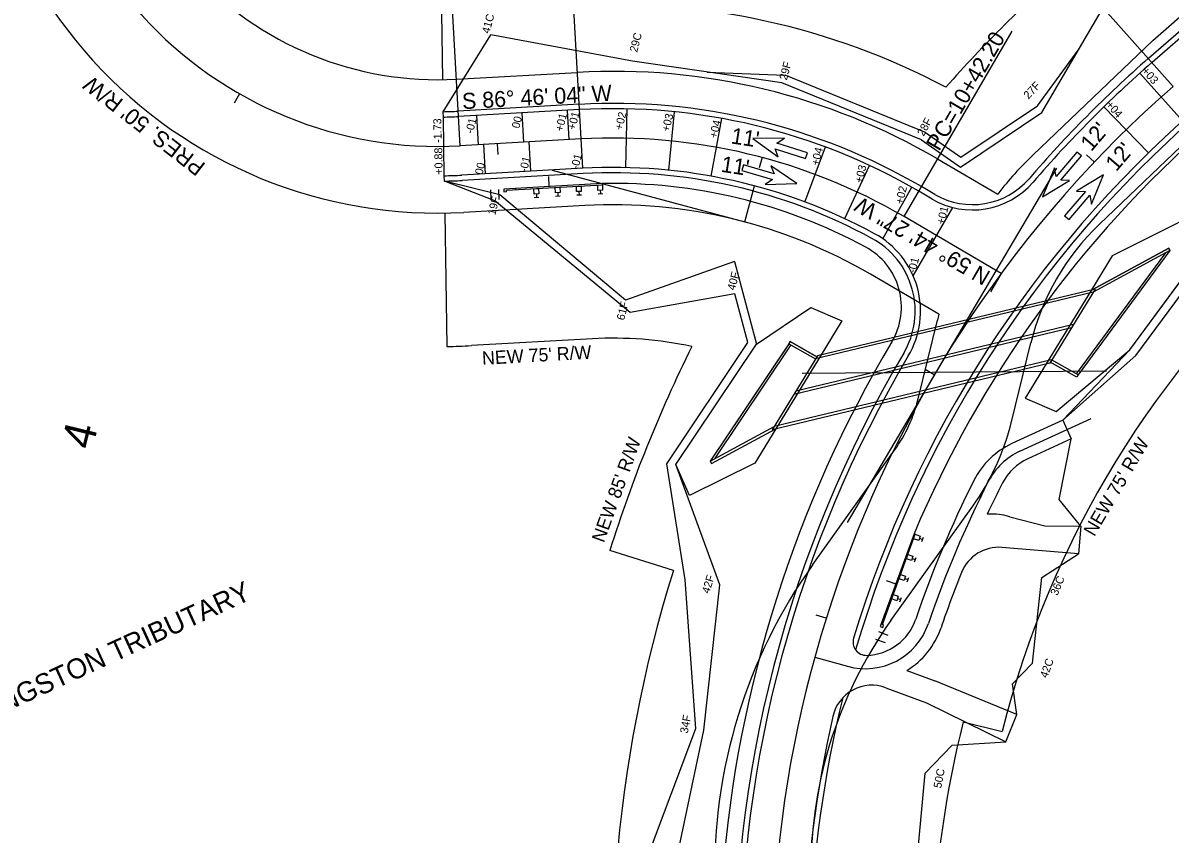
# Model space of a CAD drawing. Extents: x 1579440 to 1580937, y 1116374 to 1119566.
# Drawn here: x 1579773.5 to 1580203.4, y 1117456.1 to 1117760.1 of the extents above; entities that cross this region are included whole.
import ezdxf

# ---------------------------------------------------------------- set-up
doc = ezdxf.new("R2010")
doc.units = 0
for name, color, linetype in [('BR_CENTER LINES', 7, 'Continuous'), ('RD_EX_DV_TX_Prop', 7, 'Continuous'), ('RD_EX_RW', 7, 'Continuous'), ('RD_EX_RW_TX', 7, 'Continuous'), ('RD_EX_SU_Telecom', 7, 'Continuous'), ('RD_EX_VEG', 7, 'Continuous'), ('RD_HC_Cl', 7, 'Continuous'), ('RD_HC_CL_Rel', 7, 'Continuous'), ('RD_HC_Data', 7, 'Continuous'), ('RD_HC_Data_Tic', 7, 'Continuous'), ('RD_PD_ALT4_TX', 7, 'Continuous'), ('RD_PD_CstnLmt', 7, 'Continuous'), ('RD_PD_CstnLmt_TX', 7, 'Continuous'), ('RD_PD_DR_ErosCtrl', 7, 'Continuous'), ('RD_PD_DR_FlowCtrl', 7, 'Continuous'), ('RD_PD_Driveway', 7, 'Continuous'), ('RD_PD_Final_TrvlWay', 7, 'Continuous'), ('RD_PD_Final_TX', 7, 'Continuous'), ('RD_PD_GR', 7, 'Continuous'), ('RD_PD_PatLn1', 7, 'Continuous'), ('RD_PD_PaveShd', 7, 'Continuous'), ('RD_PD_RW', 7, 'Continuous'), ('RD_Sketch1', 7, 'Continuous')]:
    doc.layers.add(name, color=color, linetype=linetype)

# ---------------------------------------------------------------- blocks, each defined once
blk = doc.blocks.new('Guardrail_MT2_Leading_with_Buffer')
at = {"layer": 'RD_PD_GR'}
for p, q in [((17.52, 4.7), (15.77, 4.61)), ((16.72, 3.41), (16.65, 4.66)), ((25.51, 5.13), (23.76, 5.04)), ((24.7, 3.84), (24.64, 5.09)), ((38.94, 2.11), (38.74, 5.85)), ((41.94, 2.27), (41.74, 6.01)), ((1.55, 3.84), (-0.2, 3.74)), ((-0.13, 2.5), (1.61, 2.59)), ((-0.03, 0.5), (-0.13, 2.5)), ((35.92, 2.44), (-0.03, 0.5)), ((1.72, 0.59), (-0.03, 0.5)), ((-0.03, 0.5), (0, 0)), ((0, 0), (36.95, 2)), ((0.74, 2.54), (0.67, 3.79)), ((1.61, 2.59), (1.72, 0.59)), ((9.53, 4.27), (7.79, 4.18)), ((7.85, 2.93), (9.6, 3.02)), ((7.96, 0.93), (7.85, 2.93)), ((9.71, 1.03), (7.96, 0.93)), ((8.73, 2.98), (8.66, 4.22)), ((9.6, 3.02), (9.71, 1.03)), ((15.84, 3.36), (17.59, 3.45)), ((15.95, 1.36), (15.84, 3.36)), ((17.7, 1.46), (15.95, 1.36)), ((17.59, 3.45), (17.7, 1.46)), ((20.17, -2.67), (19.97, 1.08)), ((23.83, 3.79), (25.58, 3.89)), ((23.94, 1.79), (23.83, 3.79)), ((25.69, 1.89), (23.94, 1.79)), ((25.58, 3.89), (25.69, 1.89)), ((32.43, 2.25), (32.45, 1.75)), ((36.89, 3), (35.89, 2.94)), ((35.89, 2.94), (35.92, 2.44)), ((36.95, 2), (36.89, 3))]:
    blk.add_line(p, q, dxfattribs=at)

msp = doc.modelspace()

# ---------------------------------------------------------------- linework, layer by layer
at = {"layer": 'BR_CENTER LINES'}
for p, q in [((1580160.85, 1117705.68), (1580082.37, 1117572.94)), ((1580179.56, 1117629.56), (1580065.5, 1117628.75))]:
    msp.add_line(p, q, dxfattribs=at)
at = {"layer": 'RD_EX_RW'}
for p, q in [((1580196.94, 1117753.53), (1580281.34, 1117827.39)), ((1580152.08, 1117710.69), (1580196.94, 1117753.53)), ((1579935.89, 1117738.99), (1579981.24, 1117741.55)), ((1580176.94, 1117684.65), (1580221.24, 1117726.96)), ((1580116.29, 1117709.09), (1580138.85, 1117695.93)), ((1579984.06, 1117691.63), (1579938.71, 1117689.07)), ((1580116.8, 1117650.91), (1580091.09, 1117665.9)), ((1580109.02, 1117619.23), (1580116.24, 1117648.72)), ((1580143.99, 1117610.66), (1580151.21, 1117640.16)), ((1580069.52, 1117557.1), (1580100.19, 1117599.99)), ((1580098.8, 1117536.16), (1580129.47, 1117579.05))]:
    msp.add_line(p, q, dxfattribs=at)
for centre, radius, start, end in [((1579928.87, 1117863.31), 174.52, 171.1236, 273.2323), ((1579928.87, 1117863.31), 124.52, 171.1236, 273.2323), ((1579994.83, 1117500.9), 241.03, 59.7409, 93.2323), ((1580240.27, 1117618.34), 127.69, 133.6822, 142.5831), ((1579994.83, 1117500.9), 191.03, 59.7409, 93.2323), ((1580240.27, 1117618.34), 91.69, 133.6822, 166.2368), ((1580240.27, 1117618.34), 127.69, 165.2247, 166.2368), ((1580054.66, 1117632.54), 55.96, 324.4316, 346.2368), ((1580054.66, 1117632.54), 91.96, 324.4316, 346.2368), ((1580229.76, 1117442.52), 197, 144.4316, 181.4941), ((1580229.76, 1117442.52), 161, 144.4316, 181.4941)]:
    msp.add_arc(centre, radius, start, end, dxfattribs=at)
at = {"layer": 'RD_EX_SU_Telecom'}
for p, q in [((1580201.66, 1117673.87), (1580168.27, 1117628.57)), ((1580203.38, 1117674.8), (1580169, 1117628.15)), ((1580202.91, 1117675.68), (1580174.18, 1117660.08)), ((1580203.38, 1117674.8), (1580174.55, 1117659.14)), ((1580203.38, 1117674.8), (1580202.91, 1117675.68)), ((1580175.28, 1117660.35), (1580071.24, 1117635.36)), ((1580175.28, 1117660.35), (1580158.29, 1117632.61)), ((1580174.55, 1117659.14), (1580070.5, 1117634.15)), ((1580173.91, 1117660.02), (1580156.92, 1117632.28)), ((1580166.42, 1117645.88), (1580062.38, 1117620.89)), ((1580167.16, 1117647.08), (1580063.12, 1117622.09)), ((1580060.5, 1117639.83), (1580031.07, 1117595.84)), ((1580061.23, 1117639.42), (1580032.64, 1117596.69)), ((1580060.5, 1117639.83), (1580061, 1117640.7)), ((1580060.5, 1117639.83), (1580070.5, 1117634.15)), ((1580061, 1117640.7), (1580071.03, 1117635.01)), ((1580071.24, 1117635.36), (1580054.25, 1117607.62)), ((1580072.62, 1117635.69), (1580055.63, 1117607.95)), ((1580158.29, 1117632.61), (1580054.25, 1117607.62)), ((1580159.03, 1117633.82), (1580054.99, 1117608.83)), ((1580168.51, 1117627.29), (1580158.51, 1117632.96)), ((1580169, 1117628.15), (1580159.03, 1117633.82)), ((1580169, 1117628.15), (1580168.51, 1117627.29)), ((1580031.07, 1117595.84), (1580054.99, 1117608.83)), ((1580031.54, 1117594.96), (1580055.35, 1117607.89)), ((1580031.07, 1117595.84), (1580031.54, 1117594.96))]:
    msp.add_line(p, q, dxfattribs=at)
at = {"layer": 'RD_HC_Cl'}
for p, q in [((1579982.65, 1117716.59), (1579937.3, 1117714.03)), ((1579982.65, 1117716.59), (1579937.3, 1117714.03)), ((1580140.15, 1117666.23), (1580103.69, 1117687.5)), ((1580140.15, 1117666.23), (1580103.69, 1117687.5))]:
    msp.add_line(p, q, dxfattribs=at)
for centre, radius, start, end in [((1579928.87, 1117863.31), 149.52, 171.1236, 273.2323), ((1579928.87, 1117863.31), 149.52, 171.1236, 273.2323), ((1579994.83, 1117500.9), 216.03, 59.7409, 93.2323), ((1579994.83, 1117500.9), 216.03, 59.7409, 93.2323)]:
    msp.add_arc(centre, radius, start, end, dxfattribs=at)
at = {"layer": 'RD_HC_CL_Rel'}
for p, q in [((1580147.11, 1117599.56), (1580173.86, 1117611.88)), ((1580070.23, 1117522.38), (1580082.5, 1117518.99))]:
    msp.add_line(p, q, dxfattribs=at)
for centre, radius, start, end in [((1580494.33, 1117405.17), 440, 131.1901, 190.2447), ((1580157.57, 1117576.85), 25, 114.7328, 152.988), ((1580494.33, 1117405.17), 403, 152.988, 161.2024), ((1580089.16, 1117543.08), 25, 254.5511, 341.2024)]:
    msp.add_arc(centre, radius, start, end, dxfattribs=at)
at = {"layer": 'RD_HC_Data'}
for p, q in [((1579982.65, 1117716.59), (1579975.95, 1117835.33)), ((1579937.3, 1117714.03), (1579930.72, 1117830.53)), ((1580204.6, 1117736.25), (1580127.53, 1117822.95)), ((1580103.69, 1117687.5), (1580144.19, 1117756.92))]:
    msp.add_line(p, q, dxfattribs=at)
at = {"layer": 'RD_HC_Data_Tic'}
for p, q in [((1579854.65, 1117733.51), (1579852.67, 1117730.04)), ((1579951.18, 1117714.81), (1579951.41, 1117710.82)), ((1580050.49, 1117709.64), (1580049.46, 1117705.77)), ((1580175.03, 1117707.91), (1580172.13, 1117710.66)), ((1580140.15, 1117666.23), (1580136.11, 1117659.32)), ((1580115.03, 1117628.18), (1580111.58, 1117630.2)), ((1580074.54, 1117536.98), (1580070.72, 1117538.17))]:
    msp.add_line(p, q, dxfattribs=at)
at = {"layer": 'RD_PD_ALT4_TX'}
for p, q in [((1580192.05, 1117741.22), (1580208.1, 1117723.38)), ((1579944.19, 1117714.41), (1579943.57, 1117725.4)), ((1579961.17, 1117715.37), (1579960.55, 1117726.36)), ((1579978.14, 1117716.33), (1579977.52, 1117727.31)), ((1579983.27, 1117705.6), (1579982.03, 1117727.57)), ((1579999.4, 1117705.88), (1579999.89, 1117727.87)), ((1580015.5, 1117704.89), (1580017.72, 1117726.77)), ((1580178.56, 1117728.58), (1580195.33, 1117711.41)), ((1580031.47, 1117702.63), (1580035.4, 1117724.28)), ((1579946.81, 1117703.55), (1579946.19, 1117714.53)), ((1579963.78, 1117704.5), (1579963.16, 1117715.49)), ((1580066.57, 1117692.97), (1580074.27, 1117713.58)), ((1580081.45, 1117686.74), (1580090.75, 1117706.68)), ((1580095.71, 1117679.21), (1580106.63, 1117698.5)), ((1580107.12, 1117665.33), (1580122.04, 1117690.9))]:
    msp.add_line(p, q, dxfattribs=at)
at = {"layer": 'RD_PD_CstnLmt'}
for p, q in [((1580155.41, 1117726.51), (1580183.29, 1117774.31)), ((1579931.01, 1117726.8), (1579948.88, 1117755.58)), ((1580001.96, 1117745.69), (1579948.88, 1117755.58)), ((1580057.96, 1117737.67), (1580001.96, 1117745.69)), ((1580110.29, 1117716.3), (1580057.96, 1117737.67)), ((1580124.9, 1117706.07), (1580155.41, 1117726.51)), ((1580110.29, 1117716.3), (1580124.9, 1117706.07)), ((1579952.26, 1117695.71), (1579931.41, 1117700.81)), ((1579999.36, 1117656.23), (1579952.26, 1117695.71)), ((1580188.37, 1117637.58), (1580223.44, 1117685.16)), ((1580040.1, 1117670.68), (1579999.36, 1117656.23)), ((1580040.1, 1117670.68), (1580048.41, 1117639.74)), ((1580018.2, 1117594.58), (1580048.41, 1117639.74)), ((1580163.18, 1117611.18), (1580188.37, 1117637.58)), ((1580161.89, 1117581.53), (1580166.38, 1117604.22)), ((1580034.6, 1117549.51), (1580018.2, 1117594.58)), ((1580169.96, 1117571.45), (1580161.89, 1117581.53)), ((1580155.34, 1117552.26), (1580169.07, 1117561.16)), ((1580028.63, 1117495.02), (1580034.6, 1117549.51)), ((1580154.42, 1117544.41), (1580155.34, 1117552.26)), ((1580151.88, 1117520.21), (1580154.42, 1117544.41)), ((1580144.3, 1117512.45), (1580151.88, 1117520.21)), ((1580146.02, 1117500.94), (1580144.3, 1117512.45)), ((1580017.5, 1117441.94), (1580028.63, 1117495.02)), ((1580111.64, 1117479.01), (1580121.79, 1117489.4)), ((1580121.79, 1117489.4), (1580141.83, 1117490.72)), ((1580107.63, 1117434.99), (1580111.64, 1117479.01))]:
    msp.add_line(p, q, dxfattribs=at)
at = {"layer": 'RD_PD_DR_ErosCtrl'}
for p, q in [((1580153.74, 1117729), (1580169.35, 1117750.41)), ((1580029.96, 1117741.68), (1580059.1, 1117740.45)), ((1580111.73, 1117718.95), (1580059.1, 1117740.45)), ((1580124.94, 1117709.71), (1580153.74, 1117729)), ((1580111.73, 1117718.95), (1580124.94, 1117709.71)), ((1580190.57, 1117635.5), (1580244.53, 1117708.32)), ((1579950.33, 1117693.41), (1579931.41, 1117700.81)), ((1580001.03, 1117651.52), (1579950.33, 1117693.41)), ((1580040.25, 1117658.58), (1580001.03, 1117651.52)), ((1580045.16, 1117640.27), (1580040.25, 1117658.58)), ((1580014.79, 1117594.89), (1580045.16, 1117640.27)), ((1580163.18, 1117611.18), (1580190.57, 1117635.5)), ((1580021.65, 1117551.4), (1580014.79, 1117594.89)), ((1580025.7, 1117495.64), (1580021.65, 1117551.4)), ((1580004.66, 1117439.88), (1580025.7, 1117495.64))]:
    msp.add_line(p, q, dxfattribs=at)
at = {"layer": 'RD_PD_DR_FlowCtrl'}
for points in [[(1580156.92, 1117632.28), (1580149.08, 1117619.49), (1580160.67, 1117614.49), (1580188.37, 1117637.58), (1580223.44, 1117685.16), (1580211.22, 1117687.59), (1580181.75, 1117672.81), (1580173.91, 1117660.02), (1580174.18, 1117660.08), (1580202.91, 1117675.68), (1580203.38, 1117674.8), (1580169, 1117628.15), (1580168.51, 1117627.29), (1580158.51, 1117632.96), (1580158.29, 1117632.61)], [(1580055.63, 1117607.95), (1580047.79, 1117595.16), (1580023.23, 1117583.05), (1580018.2, 1117594.58), (1580048.41, 1117639.74), (1580068.83, 1117653.49), (1580080.45, 1117648.48), (1580072.62, 1117635.69), (1580071.24, 1117635.36), (1580071.03, 1117635.01), (1580061, 1117640.7), (1580060.88, 1117640.5), (1580060.5, 1117639.83), (1580060.38, 1117639.63), (1580031.07, 1117595.84), (1580031.54, 1117594.96), (1580055.35, 1117607.89)], [(1580055.63, 1117607.95), (1580047.79, 1117595.16), (1580023.23, 1117583.05), (1580018.2, 1117594.58), (1580048.41, 1117639.74), (1580068.83, 1117653.49), (1580080.45, 1117648.48), (1580072.62, 1117635.69), (1580071.24, 1117635.36), (1580071.03, 1117635.01), (1580061, 1117640.7), (1580060.88, 1117640.5), (1580060.5, 1117639.83), (1580060.38, 1117639.63), (1580031.07, 1117595.84), (1580031.54, 1117594.96), (1580055.35, 1117607.89)]]:
    msp.add_lwpolyline(points, close=True, dxfattribs=at)
at = {"layer": 'RD_PD_Driveway'}
for p, q in [((1580163.18, 1117611.18), (1580144.16, 1117602.42)), ((1580163.18, 1117611.18), (1580166.38, 1117604.22)), ((1580166.38, 1117604.22), (1580150.07, 1117596.7)), ((1580143.39, 1117575.02), (1580141.94, 1117575.4)), ((1580143.39, 1117575.02), (1580156.49, 1117571.59)), ((1580156.49, 1117571.59), (1580169.96, 1117571.45)), ((1580169.96, 1117571.45), (1580169.07, 1117561.16)), ((1580169.07, 1117561.16), (1580140.38, 1117563.53)), ((1580104.74, 1117517.45), (1580115.25, 1117513.52)), ((1580096.9, 1117510.95), (1580112.16, 1117505.25)), ((1580146.02, 1117500.94), (1580115.25, 1117513.52)), ((1580112.16, 1117505.25), (1580141.83, 1117490.72)), ((1580141.83, 1117490.72), (1580146.02, 1117500.94))]:
    msp.add_line(p, q, dxfattribs=at)
for centre, radius, start, end in [((1580156.71, 1117575.17), 30, 114.7328, 153.2739), ((1580158.43, 1117578.54), 20, 114.7328, 152.7003), ((1580494.33, 1117405.17), 408, 153.2739, 161.2024), ((1580494.33, 1117405.17), 398, 152.7003, 154.5898), ((1580136.87, 1117556.06), 20, 75.3175, 95.8446), ((1580139.19, 1117548.58), 15, 85.4676, 158.0112), ((1580494.33, 1117405.17), 398, 158.0112, 161.2024), ((1580089.16, 1117543.08), 20, 271.6231, 341.2024), ((1580089.16, 1117543.08), 30, 301.2807, 341.2024), ((1580089.58, 1117528.09), 5, 163.1069, 271.6231), ((1580089.58, 1117528.09), 5, 216.5074, 271.6231), ((1580091.65, 1117496.9), 15, 69.5092, 167.1675)]:
    msp.add_arc(centre, radius, start, end, dxfattribs=at)
at = {"layer": 'RD_PD_Final_TrvlWay'}
for p, q in [((1580196.66, 1117745.32), (1580278.71, 1117817.12)), ((1579931.38, 1117702.81), (1579931.04, 1117724.8)), ((1579982.03, 1117727.57), (1579936.68, 1117725.01)), ((1579983.27, 1117705.6), (1579937.92, 1117703.04)), ((1580114.23, 1117694.08), (1580109.24, 1117697))]:
    msp.add_line(p, q, dxfattribs=at)
for centre, radius, start, end in [((1580494.33, 1117405.17), 452, 131.1901, 139.2197), ((1579928.87, 1117863.31), 138.52, 270.8946, 273.2323), ((1579994.83, 1117500.9), 227.03, 59.7409, 93.2323), ((1580494.33, 1117405.17), 428, 131.1901, 163.1069), ((1579994.83, 1117500.9), 205.03, 61.5089, 93.2323), ((1579928.87, 1117863.31), 160.52, 270.8946, 273.2323), ((1580129.35, 1117720), 30, 239.7409, 319.2197), ((1580076.89, 1117652.1), 33, 329.3946, 61.5089), ((1580494.33, 1117405.17), 452, 149.3946, 180.4077), ((1580494.33, 1117405.17), 428, 167.1675, 190.2447)]:
    msp.add_arc(centre, radius, start, end, dxfattribs=at)
at = {"layer": 'RD_PD_Final_TX'}
for p, q in [((1580058.84, 1117716.84), (1580047.01, 1117716.81)), ((1580047.01, 1117716.81), (1580056.58, 1117709.85)), ((1580056.06, 1117715.06), (1580058.84, 1117716.84)), ((1580056.58, 1117709.85), (1580055.37, 1117712.92)), ((1580055.37, 1117712.92), (1580066.79, 1117709.23)), ((1580067.48, 1117711.37), (1580056.06, 1117715.06)), ((1580066.79, 1117709.23), (1580067.48, 1117711.37)), ((1580168.52, 1117711.7), (1580160.71, 1117702.58)), ((1580162.42, 1117701.12), (1580170.23, 1117710.23)), ((1580170.23, 1117710.23), (1580168.52, 1117711.7)), ((1580043.55, 1117706.9), (1580042.92, 1117704.74)), ((1580042.92, 1117704.74), (1580054.44, 1117701.38)), ((1580055.07, 1117703.54), (1580043.55, 1117706.9)), ((1580063.54, 1117699.9), (1580053.77, 1117706.58)), ((1580053.77, 1117706.58), (1580055.07, 1117703.54)), ((1580160.14, 1117705.83), (1580155.61, 1117694.9)), ((1580160.71, 1117702.58), (1580160.14, 1117705.83)), ((1580054.44, 1117701.38), (1580051.71, 1117699.52)), ((1580051.71, 1117699.52), (1580063.54, 1117699.9)), ((1580155.61, 1117694.9), (1580165.72, 1117701.05)), ((1580165.72, 1117701.05), (1580162.42, 1117701.12)), ((1580178.49, 1117703.16), (1580168.38, 1117697)), ((1580173.96, 1117692.22), (1580178.49, 1117703.16)), ((1580171.68, 1117696.94), (1580163.88, 1117687.83)), ((1580165.58, 1117686.36), (1580173.39, 1117695.48)), ((1580168.38, 1117697), (1580171.68, 1117696.94)), ((1580173.39, 1117695.48), (1580173.96, 1117692.22)), ((1580163.88, 1117687.83), (1580165.58, 1117686.36))]:
    msp.add_line(p, q, dxfattribs=at)
at = {"layer": 'RD_PD_GR'}
for centre, radius, start, end in [((1580494.33, 1117405.17), 420, 131.1901, 157.0961), ((1579994.83, 1117500.9), 199.03, 61.6551, 91.2223), ((1580077.22, 1117653.63), 25.5, 329.2197, 61.6551), ((1580494.33, 1117405.17), 460, 149.2197, 175.5909)]:
    msp.add_arc(centre, radius, start, end, dxfattribs=at)
at = {"layer": 'RD_PD_PaveShd'}
for p, q in [((1580195.35, 1117746.82), (1580277.39, 1117818.62)), ((1579981.92, 1117729.57), (1579936.57, 1117727.01)), ((1579931.04, 1117724.8), (1579931.01, 1117726.8)), ((1579983.38, 1117703.61), (1579938.04, 1117701.05)), ((1579931.41, 1117700.81), (1579931.38, 1117702.81)), ((1580115.24, 1117695.81), (1580110.24, 1117698.73))]:
    msp.add_line(p, q, dxfattribs=at)
for centre, radius, start, end in [((1580494.33, 1117405.17), 454, 131.1901, 139.2197), ((1579994.83, 1117500.9), 229.03, 59.7409, 93.2323), ((1579928.87, 1117863.31), 136.52, 270.8946, 273.2323), ((1580494.33, 1117405.17), 426, 131.1901, 163.6468), ((1579994.83, 1117500.9), 203.03, 61.5089, 93.2323), ((1579928.87, 1117863.31), 162.52, 270.8946, 273.2323), ((1580129.35, 1117720), 28, 239.7409, 319.2197), ((1580076.89, 1117652.1), 31, 329.3946, 61.5089), ((1580494.33, 1117405.17), 454, 149.3946, 181.614), ((1580494.33, 1117405.17), 426, 166.1452, 190.2447)]:
    msp.add_arc(centre, radius, start, end, dxfattribs=at)
at = {"layer": 'RD_PD_RW'}
for p, q in [((1579930.82, 1117738.8), (1579930.43, 1117763.8)), ((1579931.6, 1117688.81), (1579932.38, 1117638.82)), ((1579986.88, 1117641.71), (1579941.53, 1117639.15)), ((1580017.29, 1117554.95), (1579993.44, 1117562.44)), ((1580125.9, 1117498.23), (1580140.45, 1117494.56))]:
    msp.add_line(p, q, dxfattribs=at)
for centre, radius, start, end in [((1580494.33, 1117405.17), 500, 131.1901, 138.579), ((1579994.83, 1117500.9), 266.03, 62.0802, 93.2323), ((1580494.33, 1117405.17), 365, 131.1901, 165.8246), ((1579928.87, 1117863.31), 224.52, 270.8946, 273.2323), ((1579994.83, 1117500.9), 141.03, 77.9815, 93.2323), ((1580494.33, 1117405.17), 525, 153.5715, 162.5691), ((1580494.33, 1117405.17), 500, 162.5691, 188.6127), ((1580494.33, 1117405.17), 380, 165.8246, 190.2447)]:
    msp.add_arc(centre, radius, start, end, dxfattribs=at)
at = {"layer": 'RD_Sketch1'}
for p, q in [((1579971.77, 1117704.95), (1580044.05, 1117685.48)), ((1580044.05, 1117685.48), (1580047.66, 1117699.01))]:
    msp.add_line(p, q, dxfattribs=at)

# ---------------------------------------------------------------- block references
at = {"layer": 'RD_PD_GR', "rotation": -179.86170939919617}
msp.add_blockref('Guardrail_MT2_Leading_with_Buffer', (1579990.59, 1117699.89), dxfattribs=at)
at = {"layer": 'RD_PD_PatLn1', "rotation": -113.13190743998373}
msp.add_blockref('Guardrail_MT2_Leading_with_Buffer', (1580107.44, 1117568.63), dxfattribs=at)

# ---------------------------------------------------------------- texts
at = {"layer": 'RD_EX_DV_TX_Prop'}
msp.add_text('4', height=12, rotation=76.2368, dxfattribs=at).set_placement((1579799.45, 1117599.83))
at = {"layer": 'RD_EX_RW_TX'}
msp.add_text("PRES. 50' R/W", height=6, rotation=142.1646, dxfattribs=at).set_placement((1579842.27, 1117707.06))
at = {"layer": 'RD_EX_VEG'}
for s, p in [('-1.73', (1579930.39, 1117715.17)), ('+0.88', (1579930.78, 1117703.22))]:
    msp.add_text(s, height=3, rotation=90.8946, dxfattribs=at).set_placement(p)
at = {"layer": 'RD_HC_Data'}
for s, height, rotation, p in [('PC=10+42.20', 6, 59.7409, (1580116.85, 1117711.74)), ('S 86%%d 46\' 04" W', 6, 3.2323, (1579938.21, 1117727.75)), ('N 59%%d 44\' 27" W', 6, 149.7409, (1580136.53, 1117666.62)), ('LANGSTON TRIBUTARY', 7.5, 24.6305, (1579755.17, 1117496.46))]:
    msp.add_text(s, height=height, rotation=rotation, dxfattribs=at).set_placement(p)
at = {"layer": 'RD_PD_ALT4_TX'}
for s, rotation, p in [('+03', 311.1901, (1580192.59, 1117741.94)), ('+04', 311.1901, (1580179.17, 1117729.34)), ('00', 76.2368, (1579959.49, 1117720.36)), ('+01', 76.2368, (1579975.8, 1117719.21)), ('+01', 76.2368, (1579980.49, 1117719.78)), ('+02', 76.2368, (1579998.08, 1117719.71)), ('+03', 76.2368, (1580015.68, 1117719.1)), ('-01', 76.2368, (1579942.13, 1117718.39)), ('+04', 76.2368, (1580033.53, 1117716.65)), ('+04', 76.2368, (1580071.73, 1117706.4)), ('00', 76.2368, (1579945.67, 1117703)), ('-01', 76.2368, (1579962.35, 1117704)), ('-01', 76.2368, (1579981.65, 1117705.01)), ('+03', 76.2368, (1580088.06, 1117699.86)), ('+02', 76.2368, (1580103.23, 1117691.94)), ('+01', 76.2368, (1580118.76, 1117684.32)), ('-01', 76.2368, (1580108, 1117666.18))]:
    msp.add_text(s, height=3, rotation=rotation, dxfattribs=at).set_placement(p)
at = {"layer": 'RD_PD_CstnLmt_TX'}
for s, rotation, p in [('41C', 74.8372, (1579948.27, 1117755.88)), ('29C', 75.3853, (1580003.65, 1117748.87)), ('29F', 75.0701, (1580059.77, 1117738.43)), ('27F', 46.5256, (1580150.33, 1117731.33)), ('28F', 61.809, (1580111.06, 1117717.39)), ('19F', 75.9522, (1579950.48, 1117687.86)), ('40F', 75.0701, (1580040.27, 1117659.66)), ('61F', 76.0456, (1579998.81, 1117648.46)), ('42F', 72.5691, (1580030.67, 1117546.06)), ('36C', 67.7248, (1580161.18, 1117545.26)), ('42C', 69.9658, (1580157.35, 1117514.37)), ('34F', 79.08, (1580022.61, 1117493.67)), ('50C', 79.08, (1580117.62, 1117473.13))]:
    msp.add_text(s, height=3, rotation=rotation, dxfattribs=at).set_placement(p)
at = {"layer": 'RD_PD_Final_TX'}
for s, rotation, p in [("11'", 351.2873, (1580038.58, 1117714.95)), ("12'", 49.4293, (1580173.87, 1117711.61)), ("12'", 49.4293, (1580183.22, 1117704.08)), ("11'", 351.2873, (1580034.84, 1117704.33))]:
    msp.add_text(s, height=6, rotation=rotation, dxfattribs=at).set_placement(p)
at = {"layer": 'RD_PD_RW'}
for s, rotation, p in [("NEW 75' R/W", 3.2323, (1579945.67, 1117631.95)), ("NEW 85' R/W", 70.0782, (1579991.2, 1117565.04)), ("NEW 75' R/W", 59.6917, (1580175.03, 1117567.34))]:
    msp.add_text(s, height=5, rotation=rotation, dxfattribs=at).set_placement(p)

doc.saveas('drawing.dxf')
